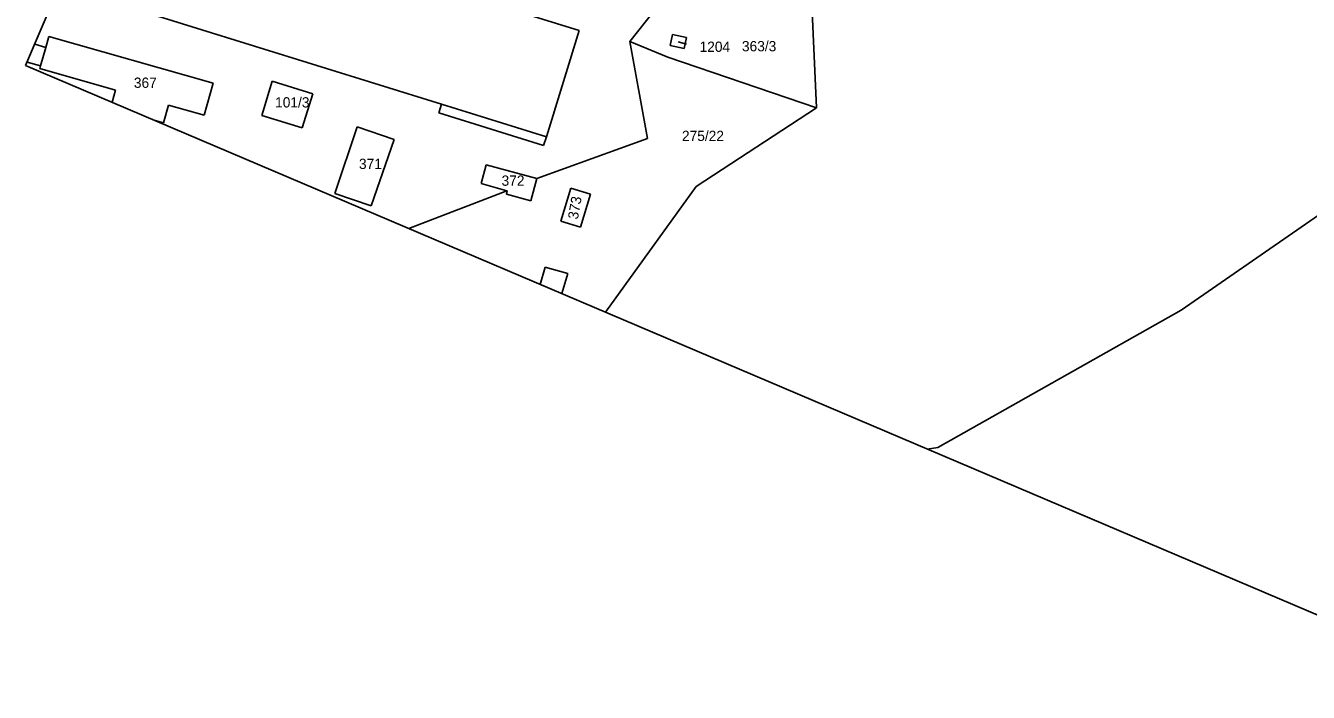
# Model space of a CAD drawing. Extents: x -805826 to -803822, y -1165880 to -1164382.
# Drawn here: x -805826.1 to -805401.4, y -1165376.6 to -1165156 of the extents above; entities that cross this region are included whole.
import ezdxf

# ---------------------------------------------------------------- set-up
doc = ezdxf.new("R2010")
doc.units = 0
for name, color, linetype in [('formát', 7, 'Continuous'), ('kn_celek - Cisla parcel pomocna', 7, 'Continuous'), ('kn_celek - Cisla pozemkovych parcel', 7, 'Continuous'), ('kn_celek - Cisla stavebnich parcel', 7, 'Continuous'), ('kn_celek - Hranice KU 1_2880', 7, 'Continuous'), ('kn_celek - Hranice parcel', 7, 'Continuous'), ('kn_celek - Vnitrni kresby', 7, 'Continuous')]:
    doc.layers.add(name, color=color, linetype=linetype)

msp = doc.modelspace()

# ---------------------------------------------------------------- linework, layer by layer
at = {"layer": 'formát'}
for p in [(-805491.17, -1164382.07), (-805269.53, -1165405.94)]:
    msp.add_line(p, (-805826.05, -1165169.15), dxfattribs=at)
at = {"layer": 'kn_celek - Cisla parcel pomocna'}
msp.add_line((-805610.09, -1165161.35), (-805607.26, -1165162.12), dxfattribs=at)
at = {"layer": 'kn_celek - Hranice KU 1_2880'}
for p, q in [((-805392, -1165214.47), (-805443.52, -1165250.14)), ((-805443.52, -1165250.14), (-805524.15, -1165295.57)), ((-805524.15, -1165295.57), (-805527.67, -1165296.11))]:
    msp.add_line(p, q, dxfattribs=at)
at = {"layer": 'kn_celek - Hranice parcel'}
for p, q in [((-805642.84, -1165157.55), (-805719.7, -1165133.74)), ((-805566.11, -1165142.85), (-805564.24, -1165183.13)), ((-805791.54, -1165149.95), (-805688.4, -1165181.93)), ((-805626.04, -1165161.21), (-805618.03, -1165151.04)), ((-805653.69, -1165192.73), (-805642.84, -1165157.55)), ((-805819.38, -1165163.17), (-805823.06, -1165162.11)), ((-805819.38, -1165163.17), (-805818.39, -1165159.62)), ((-805818.39, -1165159.62), (-805763.98, -1165175)), ((-805626.04, -1165161.21), (-805613.53, -1165166.38)), ((-805620.18, -1165193.32), (-805626.04, -1165161.21)), ((-805612.68, -1165162.5), (-805611.9, -1165158.93)), ((-805611.9, -1165158.93), (-805607.27, -1165159.93)), ((-805607.27, -1165159.93), (-805608.05, -1165163.5)), ((-805564.24, -1165183.13), (-805613.53, -1165166.38)), ((-805608.05, -1165163.5), (-805612.68, -1165162.5)), ((-805825.57, -1165168.01), (-805821.12, -1165169.31)), ((-805821.36, -1165170.15), (-805821.12, -1165169.31)), ((-805796.34, -1165177.33), (-805821.36, -1165170.15)), ((-805763.98, -1165175), (-805766.97, -1165185.64)), ((-805747.87, -1165185.67), (-805744.4, -1165174.4)), ((-805744.4, -1165174.4), (-805731.01, -1165178.53)), ((-805797.46, -1165181.32), (-805796.34, -1165177.33)), ((-805731.01, -1165178.53), (-805734.48, -1165189.79)), ((-805778.73, -1165182.3), (-805780.41, -1165188.13)), ((-805766.97, -1165185.64), (-805778.73, -1165182.3)), ((-805688.4, -1165181.93), (-805689.27, -1165184.79)), ((-805564.24, -1165183.13), (-805604.14, -1165209.26)), ((-805780.41, -1165188.13), (-805783.5, -1165187.26)), ((-805734.48, -1165189.79), (-805747.87, -1165185.67)), ((-805689.27, -1165184.79), (-805654.59, -1165195.63)), ((-805723.71, -1165211.48), (-805716.28, -1165189.45)), ((-805716.28, -1165189.45), (-805704.06, -1165193.63)), ((-805704.06, -1165193.63), (-805711.66, -1165215.6)), ((-805656.82, -1165206.59), (-805620.18, -1165193.32)), ((-805654.59, -1165195.63), (-805653.69, -1165192.73)), ((-805675.3, -1165208.27), (-805673.59, -1165202.01)), ((-805673.59, -1165202.01), (-805656.82, -1165206.59)), ((-805666.76, -1165210.61), (-805675.3, -1165208.27)), ((-805656.82, -1165206.59), (-805658.84, -1165214)), ((-805711.66, -1165215.6), (-805723.71, -1165211.48)), ((-805666.76, -1165210.61), (-805699.24, -1165223.11)), ((-805666.92, -1165211.79), (-805666.61, -1165210.66)), ((-805658.84, -1165214), (-805666.92, -1165211.79)), ((-805666.61, -1165210.66), (-805666.76, -1165210.61)), ((-805648.89, -1165220.64), (-805645.61, -1165209.79)), ((-805645.61, -1165209.79), (-805639.06, -1165211.72)), ((-805639.06, -1165211.72), (-805642.4, -1165222.63)), ((-805604.14, -1165209.26), (-805634.14, -1165250.81)), ((-805642.4, -1165222.63), (-805648.89, -1165220.64)), ((-805655.76, -1165241.61), (-805654.05, -1165235.86)), ((-805654.05, -1165235.86), (-805646.61, -1165238.04)), ((-805646.61, -1165238.04), (-805648.57, -1165244.67))]:
    msp.add_line(p, q, dxfattribs=at)
at = {"layer": 'kn_celek - Vnitrni kresby'}
for p, q in [((-805821.12, -1165169.31), (-805819.38, -1165163.17)), ((-805688.4, -1165181.93), (-805653.69, -1165192.73))]:
    msp.add_line(p, q, dxfattribs=at)

# ---------------------------------------------------------------- texts
at = {"layer": 'kn_celek - Cisla parcel pomocna'}
msp.add_text('1204', height=3.4, dxfattribs=at).set_placement((-805602.97, -1165164.66))
at = {"layer": 'kn_celek - Cisla pozemkovych parcel'}
for s, height, p in [('1204', 0.005, (-805610.09, -1165161.35)), ('363/3', 3.4, (-805588.95, -1165164.47)), ('275/22', 3.4, (-805608.8, -1165194.16))]:
    msp.add_text(s, height=height, dxfattribs=at).set_placement(p)
at = {"layer": 'kn_celek - Cisla stavebnich parcel'}
for s, p in [('367', (-805790.23, -1165176.56)), ('101/3', (-805743.48, -1165183.06)), ('371', (-805715.72, -1165203.42)), ('372', (-805668.52, -1165208.97))]:
    msp.add_text(s, height=3.4, dxfattribs=at).set_placement(p)
msp.add_text('373', height=3.4, rotation=80.217, dxfattribs=at).set_placement((-805643.26, -1165220.26))

doc.saveas('drawing.dxf')
